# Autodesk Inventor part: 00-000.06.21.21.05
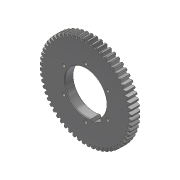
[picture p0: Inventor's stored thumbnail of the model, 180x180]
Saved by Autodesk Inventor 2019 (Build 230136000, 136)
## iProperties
Created: 2019-01
Part Number: 00-000.06.21.21.05
Material: Steel, Non-Alloy
Document SubType Name: Modeling
Designer: m.vorobev
Density: 7.85 g/cm^3
Appearance: Steel
Author: m.vorobev
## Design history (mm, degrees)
sketch "Sketch1"
  geometry: C1 r 143.75 at (0, 0) reference; C2 r 140.954 at (0, 0) reference; C3 r 150 at (0, 0) reference; A1 r 155 centre (0, 0) between (-6.149, 154.878) and (6.149, 154.878) reference; 32 further points
  constraints: 4 centre point, 2 point on circle, 71 other
extrude "Extrusion1" join sketch "Sketch1" distance "d0" = 30 (= FaceWidth); taper "d1" = 0 deg
chamfer "Chamfer1" distance "d2" = 2; stored, may be unused: second distance "d3" = 2, angle "d4" = 45 deg
sketch "Sketch2"
  geometry: C1 r 155 at (0, 0) reference; 2 further points
  constraints: 1 coincident
hole "Hole1" sketch "Sketch2" at (0, 0) diameter "d5" = 140; stored, may be unused: countersink angle "d9" = 90 deg, drill point angle "d11" = 118 deg; dims "d6" = 6, "d7" = 4, "d8" = 2, "d10" = 100.75
chamfer "Chamfer2" distance "d12" = 2; stored, may be unused: second distance "d13" = 2, angle "d14" = 45 deg
sketch "Sketch3"
  geometry: L1 (0, 0)-(0, 85)
  constraints: 2 end point, 1 vertical
  dimensions: "d15" = 85 distance of L1.start L1.end
hole "Hole2" sketch "Sketch3" at (0, 85) diameter "d16" = 11; stored, may be unused: countersink angle "d20" = 90 deg, drill point angle "d22" = 118 deg; dims "d17" = 6, "d18" = 4, "d19" = 2, "d21" = 100.75
pattern_circular "Circular Pattern1" dims angle "d24" = 360 deg
sketch "Sketch4"
  geometry: L1 (23.112, -76.03)-(54.288, -58.03); L2 (54.288, -58.03)-(27.735, -12.039); L3 (27.735, -12.039)-(-3.442, -30.039); L4 (-3.442, -30.039)-(23.112, -76.03); L5 (0, 0)-(31.98, 0); L6 (31.98, 0)-(31.98, 22.179); L7 (31.98, 22.179)-(0, 22.179); L8 (0, 22.179)-(0, 0); L9 (0, 0)-(38.7, -67.03); C1 r 70 at (0, 0) reference
  constraints: 18 end point, 4 parallel, 3 perpendicular, 1 horizontal, 1 midpoint
  dimensions: "d27" = 30 deg angle of L8 L9; "d28" = 147.4 dimension on C1 L1; "d31" = 36 distance of L1.start L1.end
extrude "Extrusion2" cut sketch "Sketch4" extent not by distance; stored distance "d29" = 10; taper "d30" = 0 deg
fillet "Fillet1" dims "d32" = 0.8
extrude "Extrusion3" cut sketch "Sketch1" extent not by distance; stored distance "d33" = 10; taper "d34" = 0 deg
body "Solid1"
pattern_circular "Circular Pattern2" dims angle "d36" = 360 deg
other parameters: "Module" = 5 [user parameter], "PressureAngle" = 20 deg [user parameter], "UnitProfileClearance" = 2.5 [user parameter], "UnitRoundRadius" = 3.5 [user parameter], "RootDiameter" = 287.5 [user parameter], "BaseDiameter" = 281.90779 [user parameter], "FaceWidth" = 30 [user parameter; used in 1 equation term], "HelixAngle" = 0 [user parameter], "UnitCorrection" = 0 [user parameter], "UnitAddendumModification" = 0 [user parameter], "CircularPitch" = 90 deg [user parameter], "UnitBacklashShift" = 0 [user parameter], "TotalToolShift" = 0 [user parameter], "IsInternal" = 0 [user parameter]
